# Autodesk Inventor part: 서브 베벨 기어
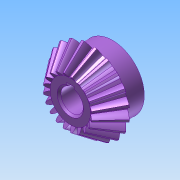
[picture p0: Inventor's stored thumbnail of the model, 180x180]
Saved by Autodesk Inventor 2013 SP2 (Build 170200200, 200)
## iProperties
Created: 2026-07
Part Number: 서브 베벨 기어
Material: Generic
Document SubType Name: Modeling
Designer: a
Density: 1 g/cm^3
Author: a
변환 표준: STEP AP214IS
전처리기: Build: 200, Release: 2013 SP2 Update 6 - Date: Thu 07/17/2014
전송 단위: 밀리미터
불확실성: 0.01
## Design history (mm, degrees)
node "서브 베벨기어1"
node "3D 스케치1"
body "Solid1"
node "기준1"
